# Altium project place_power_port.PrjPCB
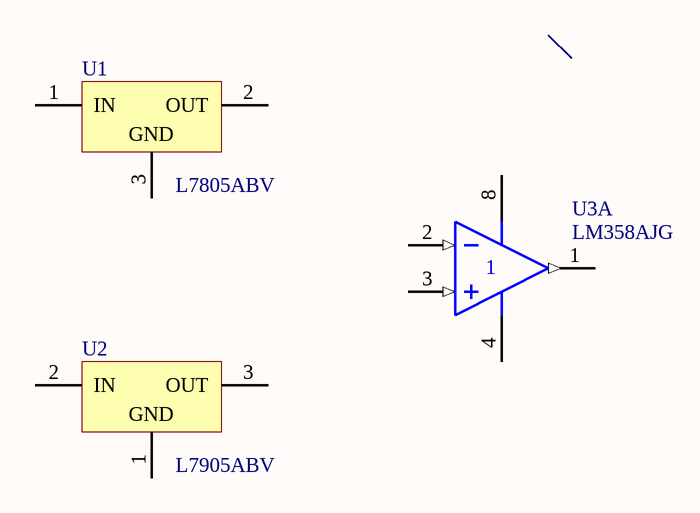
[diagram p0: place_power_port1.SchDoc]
1 sheet, 3 parts. Net scope: global (net labels, ports and power ports of the same name join across sheets).

## Sheet place_power_port1.SchDoc
size A4

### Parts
U1  L7805ABV  [TO220ABN]
U2  L7905ABV  [TO220V]
U3  LM358AJG  [JG008]  (part A of 2)

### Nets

Not connected (* = marked no-connect by the designer): U1 1(IN) 2(OUT) 3(GND); U2 1(GND) 2(IN) 3(OUT); U3 1(OUT) 2(IN-) 3(IN+) 4(V-) 8(V+)

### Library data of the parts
U1 = L7805ABV: Precision 1A Regulator; Note: Tab is connected to pin 3 (GND).
U2 = L7905ABV: ?2%Negative Voltage Regulator; Note: Tab is connected to pin 3 (IN).
U3 = LM358AJG: Dual Operational Amplifier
